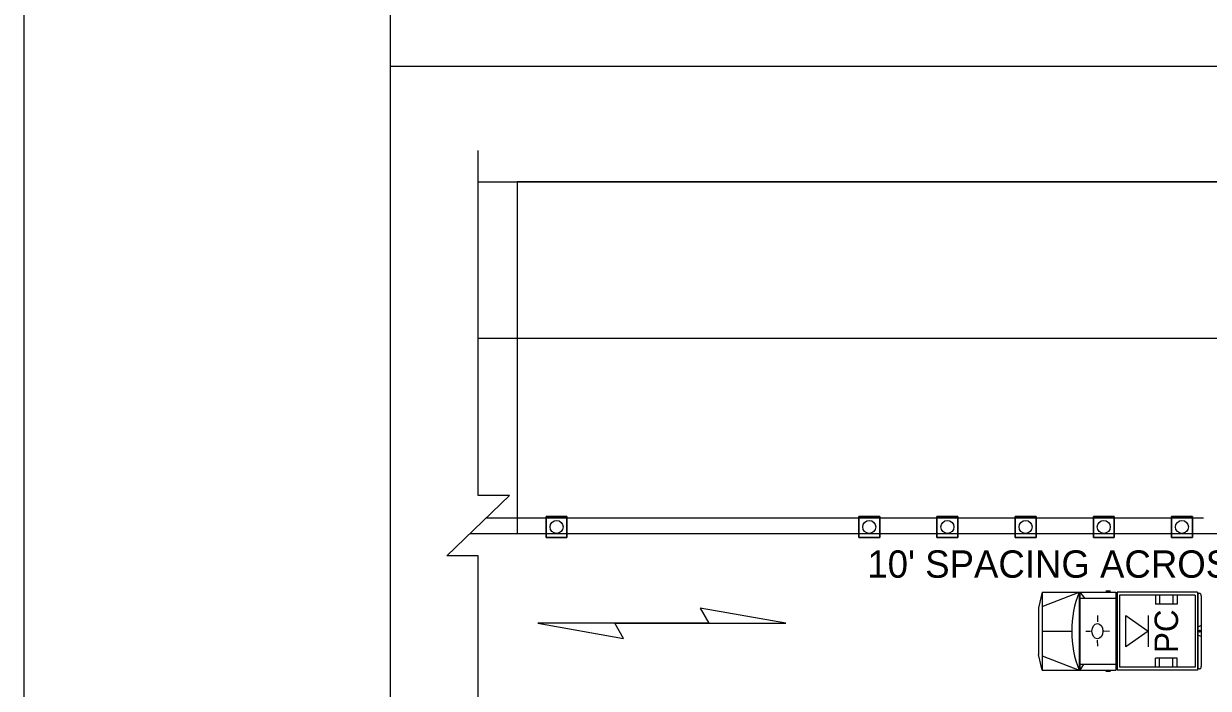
# Model space of a CAD drawing. Extents: x 99999.1 to 100095.7, y 99995 to 100010.7.
# Drawn here: x 100059.062 to 100062.093, y 100004.389 to 100006.09 of the extents above; entities that cross this region are included whole.
import ezdxf

# ---------------------------------------------------------------- set-up
doc = ezdxf.new("R2010")
doc.units = 0
for name, color, linetype in [('RD_ED_ShoulderPavedEdge', 7, 'Continuous'), ('RD_MK_LineDblYellowCenter', 7, 'Continuous'), ('RD_MK_LineEdgeWhite', 7, 'Continuous'), ('SH_GI_PlotLimits', 7, 'Continuous'), ('SH_GI_SheetBorder', 7, 'Continuous'), ('TR_WZ_MotoristVehicle', 7, 'Continuous'), ('TR_WZ_PortableSignMountBlk-Wht', 7, 'Continuous'), ('TR_WZ_TrafficCone', 7, 'Continuous'), ('TR_WZ_WorkZoneDetails', 7, 'Continuous'), ('TR_WZ_WorkZoneTextCurrent', 7, 'Continuous')]:
    doc.layers.add(name, color=color, linetype=linetype)

msp = doc.modelspace()

# ---------------------------------------------------------------- linework, layer by layer
at = {"layer": 'RD_ED_ShoulderPavedEdge'}
msp.add_line((100060.225, 100005.6849), (100065.025, 100005.6849), dxfattribs=at)
at = {"layer": 'RD_MK_LineDblYellowCenter'}
for p, q in [((100060.2457, 100004.8249), (100062.0812, 100004.8249)), ((100060.2043, 100004.7849), (100062.0812, 100004.7849))]:
    msp.add_line(p, q, dxfattribs=at)
at = {"layer": 'RD_MK_LineEdgeWhite'}
msp.add_line((100060.225, 100005.2849), (100065.025, 100005.2849), dxfattribs=at)
at = {"layer": 'SH_GI_PlotLimits'}
msp.add_lwpolyline([(100059.0625, 99999.6875), (100076.0625, 99999.6875), (100076.0625, 100010.6875), (100059.0625, 100010.6875)], close=True, dxfattribs=at)
at = {"layer": 'SH_GI_SheetBorder'}
msp.add_line((100060, 100010.375), (100060, 100000), dxfattribs=at)
at = {"layer": 'TR_WZ_MotoristVehicle'}
for p, q in [((100061.668, 100004.6349), (100061.6587, 100004.5946)), ((100061.668, 100004.6349), (100061.668, 100004.4349)), ((100061.668, 100004.6349), (100061.8569, 100004.6349)), ((100061.668, 100004.5983), (100061.7625, 100004.6349)), ((100061.7625, 100004.6349), (100061.7625, 100004.4349)), ((100061.7642, 100004.6349), (100061.7642, 100004.4349)), ((100061.7642, 100004.6349), (100061.7762, 100004.6194)), ((100061.8311, 100004.6377), (100061.8425, 100004.6377)), ((100061.8569, 100004.6349), (100061.8569, 100004.4349)), ((100062.0654, 100004.6349), (100061.8597, 100004.6349)), ((100061.8597, 100004.6349), (100061.8597, 100004.4349)), ((100062.0595, 100004.6269), (100061.8655, 100004.6269)), ((100061.8655, 100004.6269), (100061.8655, 100004.4429)), ((100061.9582, 100004.6269), (100061.9582, 100004.6039)), ((100061.9682, 100004.6269), (100061.9682, 100004.6039)), ((100062.0022, 100004.6269), (100062.0022, 100004.6039)), ((100062.0132, 100004.6269), (100062.0132, 100004.6039)), ((100062.0595, 100004.6269), (100062.0595, 100004.4429)), ((100062.0654, 100004.6349), (100062.0654, 100004.4349)), ((100062.0705, 100004.6316), (100062.0661, 100004.6316)), ((100062.0661, 100004.6316), (100062.0661, 100004.4382)), ((100061.7642, 100004.6194), (100061.8569, 100004.6194)), ((100062.0132, 100004.6039), (100061.9582, 100004.6039)), ((100062.075, 100004.6255), (100062.075, 100004.4443)), ((100061.6587, 100004.5946), (100061.6587, 100004.4753)), ((100061.8095, 100004.5746), (100061.8095, 100004.5584)), ((100062.075, 100004.549), (100062.0661, 100004.5453)), ((100062.0705, 100004.5377), (100062.0705, 100004.5321)), ((100061.668, 100004.5349), (100061.7439, 100004.5349)), ((100061.7794, 100004.5351), (100061.792, 100004.535)), ((100061.8102, 100004.4965), (100061.8099, 100004.5115)), ((100061.8236, 100004.5346), (100061.8236, 100004.5346)), ((100061.8404, 100004.5342), (100061.8255, 100004.5345)), ((100062.075, 100004.5208), (100062.0661, 100004.5246)), ((100062.0726, 100004.5349), (100062.0685, 100004.5349)), ((100061.668, 100004.4349), (100061.6587, 100004.4753)), ((100061.668, 100004.4716), (100061.7625, 100004.4349)), ((100061.7642, 100004.4504), (100061.8569, 100004.4504)), ((100061.7741, 100004.4504), (100061.7642, 100004.4349)), ((100061.9582, 100004.4429), (100061.9582, 100004.4659)), ((100062.0132, 100004.4659), (100061.9582, 100004.4659)), ((100061.9682, 100004.4429), (100061.9682, 100004.4659)), ((100062.0022, 100004.4429), (100062.0022, 100004.4659)), ((100062.0132, 100004.4429), (100062.0132, 100004.4659)), ((100061.668, 100004.4349), (100061.8569, 100004.4349)), ((100061.8311, 100004.4321), (100061.8425, 100004.4321)), ((100062.0654, 100004.4349), (100061.8597, 100004.4349)), ((100062.0595, 100004.4429), (100061.8655, 100004.4429)), ((100062.0705, 100004.4382), (100062.0661, 100004.4382))]:
    msp.add_line(p, q, dxfattribs=at)
for centre, major_axis, start_param, end_param in [((100061.8974, 100004.5349), (0, -0.2099), 4.215667, 5.208926), ((100062.0705, 100004.6255), (0, 0.0061), 4.712389, 6.283185), ((100062.0705, 100004.4443), (0, -0.0061), 0, 1.570796)]:
    msp.add_ellipse(centre, major_axis=major_axis, ratio=0.73155, start_param=start_param, end_param=end_param, dxfattribs=at)
for centre, major_axis in [((100061.8095, 100004.5349), (0, 0.0193)), ((100062.0705, 100004.5349), (0, 0.00282))]:
    msp.add_ellipse(centre, major_axis=major_axis, ratio=0.73155, dxfattribs=at)
at = {"layer": 'TR_WZ_PortableSignMountBlk-Wht'}
msp.add_line((100061.9393, 100004.5748), (100061.9393, 100004.4948), dxfattribs=at)
msp.add_lwpolyline([(100061.9393, 100004.5349), (100061.8819, 100004.4948), (100061.8819, 100004.5748)], close=True, dxfattribs=at)
at = {"layer": 'TR_WZ_TrafficCone'}
for points in [[(100060.399, 100004.8283), (100060.4524, 100004.8283), (100060.4524, 100004.7749), (100060.399, 100004.7749), (100060.399, 100004.8283)], [(100060.399, 100004.7749), (100060.4524, 100004.7749), (100060.4524, 100004.8283), (100060.399, 100004.8283), (100060.399, 100004.7749)], [(100061.199, 100004.8283), (100061.2524, 100004.8283), (100061.2524, 100004.7749), (100061.199, 100004.7749), (100061.199, 100004.8283)], [(100061.199, 100004.7749), (100061.2524, 100004.7749), (100061.2524, 100004.8283), (100061.199, 100004.8283), (100061.199, 100004.7749)], [(100061.399, 100004.8283), (100061.4524, 100004.8283), (100061.4524, 100004.7749), (100061.399, 100004.7749), (100061.399, 100004.8283)], [(100061.399, 100004.7749), (100061.4524, 100004.7749), (100061.4524, 100004.8283), (100061.399, 100004.8283), (100061.399, 100004.7749)], [(100061.599, 100004.8283), (100061.6524, 100004.8283), (100061.6524, 100004.7749), (100061.599, 100004.7749), (100061.599, 100004.8283)], [(100061.599, 100004.7749), (100061.6524, 100004.7749), (100061.6524, 100004.8283), (100061.599, 100004.8283), (100061.599, 100004.7749)], [(100061.799, 100004.8283), (100061.8524, 100004.8283), (100061.8524, 100004.7749), (100061.799, 100004.7749), (100061.799, 100004.8283)], [(100061.799, 100004.7749), (100061.8524, 100004.7749), (100061.8524, 100004.8283), (100061.799, 100004.8283), (100061.799, 100004.7749)], [(100061.999, 100004.8283), (100062.0524, 100004.8283), (100062.0524, 100004.7749), (100061.999, 100004.7749), (100061.999, 100004.8283)], [(100061.999, 100004.7749), (100062.0524, 100004.7749), (100062.0524, 100004.8283), (100061.999, 100004.8283), (100061.999, 100004.7749)]]:
    msp.add_lwpolyline(points, dxfattribs=at)
for centre in [(100060.4257, 100004.8016), (100061.2257, 100004.8016), (100061.4257, 100004.8016), (100061.6257, 100004.8016), (100061.8257, 100004.8016), (100062.0257, 100004.8016)]:
    msp.add_circle(centre, 0.0167, dxfattribs=at)
at = {"layer": 'TR_WZ_WorkZoneDetails'}
for p, q in [((100065.25, 100005.9805), (100060, 100005.9805)), ((100060.5744, 100004.5549), (100060.8156, 100004.5549)), ((100060.8156, 100004.5549), (100060.5744, 100004.5549))]:
    msp.add_line(p, q, dxfattribs=at)
msp.add_lwpolyline([(100060.225, 100003.8449), (100060.225, 100004.7275), (100060.145, 100004.7275), (100060.305, 100004.8824), (100060.225, 100004.8824), (100060.225, 100005.7649)], dxfattribs=at)
for points in [[(100060.325, 100005.6849), (100060.325, 100004.7849), (100064.925, 100004.7849), (100064.925, 100005.6849)], [(100061.0121, 100004.5549), (100060.7933, 100004.5935), (100060.8156, 100004.5549)], [(100060.3779, 100004.5549), (100060.5967, 100004.5164), (100060.5744, 100004.5549)]]:
    msp.add_lwpolyline(points, close=True, dxfattribs=at)

# ---------------------------------------------------------------- texts
at = {"layer": 'TR_WZ_MotoristVehicle'}
msp.add_text('PC', height=0.06, rotation=90, dxfattribs=at).set_placement((100062.0157, 100004.4789))
at = {"layer": 'TR_WZ_WorkZoneTextCurrent'}
msp.add_text("10' SPACING ACROSS INTERSECTION", height=0.07, dxfattribs=at).set_placement((100061.2208, 100004.6716))

doc.saveas('drawing.dxf')
